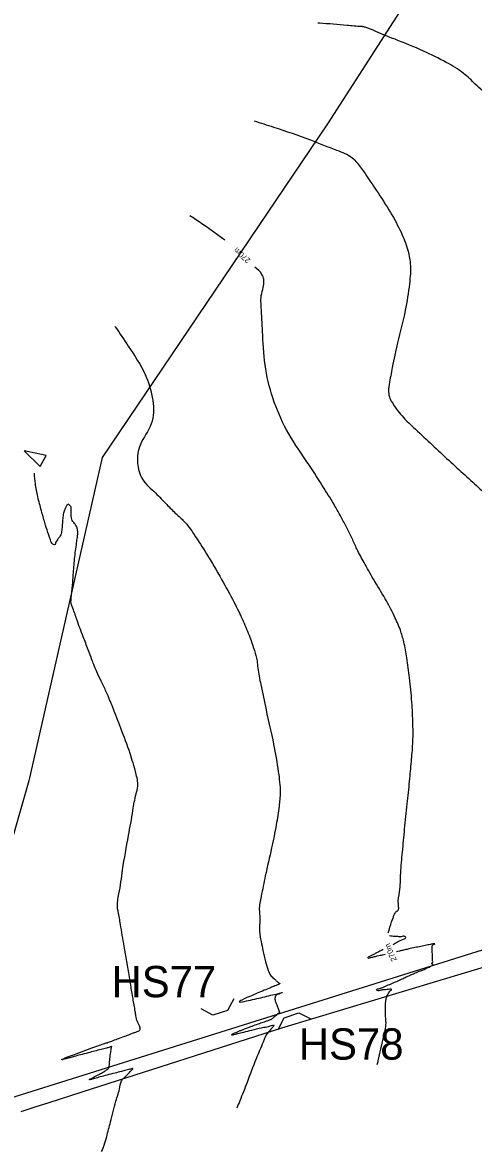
# Model space of a CAD drawing. Extents: x -478495 to -472450, y -1118050 to -1113745.
# Drawn here: x -478028.4 to -477884.4, y -1117519.1 to -1117158.4 of the extents above; entities that cross this region are included whole.
import ezdxf

# ---------------------------------------------------------------- set-up
doc = ezdxf.new("R2010")
doc.units = 0
for name, color, linetype in [('cesty', 7, 'Continuous'), ('hospodářské sjezdy', 7, 'Continuous'), ('hranice kú', 7, 'Continuous'), ('ObPÚ', 7, 'Continuous'), ('silnice', 7, 'Continuous'), ('Vrstevnice_hlavni', 7, 'Continuous'), ('Vrstevnice_popis', 7, 'Continuous'), ('Vrstevnice_vedlejsi', 7, 'Continuous')]:
    doc.layers.add(name, color=color, linetype=linetype)

msp = doc.modelspace()

# ---------------------------------------------------------------- linework, layer by layer
at = {"layer": 'cesty'}
msp.add_line((-478022.76, -1117300.27), (-478020.86, -1117296.75), dxfattribs=at)
msp.add_lwpolyline([(-478020.86, -1117296.75), (-478027.92, -1117295.21), (-478022.76, -1117300.27)], dxfattribs=at)
at = {"layer": 'hospodářské sjezdy'}
for p, q in [((-477960.95, -1117470.32), (-477962.92, -1117474.1)), ((-477967.58, -1117475.57), (-477971.37, -1117473.6)), ((-477962.92, -1117474.1), (-477967.58, -1117475.57)), ((-477944.78, -1117476.38), (-477940.15, -1117474.83)), ((-477940.15, -1117474.83), (-477936.33, -1117476.73)), ((-477946.69, -1117480.2), (-477944.78, -1117476.38))]:
    msp.add_line(p, q, dxfattribs=at)
at = {"layer": 'hranice kú'}
for p, q in [((-477902.65, -1117146.62), (-477931, -1117190.79)), ((-477931, -1117190.79), (-478003, -1117297.4)), ((-478003, -1117297.4), (-478026.36, -1117400.72)), ((-478026.36, -1117400.72), (-478038.56, -1117443.03)), ((-477945.56, -1117479.66), (-477846.46, -1117449.69)), ((-478009.33, -1117500.09), (-477945.56, -1117479.66)), ((-478019.87, -1117503.47), (-478009.33, -1117500.09)), ((-478024.36, -1117504.91), (-478019.87, -1117503.47)), ((-478028.85, -1117506.35), (-478024.36, -1117504.91))]:
    msp.add_line(p, q, dxfattribs=at)
at = {"layer": 'ObPÚ'}
for p, q in [((-477902.65, -1117146.62), (-477931, -1117190.79)), ((-477931, -1117190.79), (-478003, -1117297.4)), ((-478003, -1117297.4), (-478026.36, -1117400.72)), ((-478026.36, -1117400.72), (-478038.56, -1117443.03)), ((-477945.56, -1117479.66), (-477846.46, -1117449.69)), ((-478009.33, -1117500.09), (-477945.56, -1117479.66)), ((-478019.87, -1117503.47), (-478009.33, -1117500.09)), ((-478024.36, -1117504.91), (-478019.87, -1117503.47)), ((-478028.85, -1117506.35), (-478024.36, -1117504.91))]:
    msp.add_line(p, q, dxfattribs=at)
at = {"layer": 'silnice'}
msp.add_lwpolyline([(-478070.5, -1117514.11), (-478065.52, -1117512.47), (-477835.7, -1117440.29), (-477736.73, -1117410.08), (-477702.34, -1117405.05), (-477652.85, -1117401.69), (-477590.78, -1117403.37), (-477332.45, -1117414.28), (-477204.96, -1117416.8), (-477142.05, -1117416.8), (-477096.76, -1117410.08), (-477037.2, -1117399.17), (-476978.49, -1117379.03), (-476883.71, -1117344.63), (-476756.22, -1117298.47), (-476633.76, -1117254.83), (-476588.47, -1117242.24), (-476550.73, -1117234.69), (-476503.76, -1117230.5), (-476424.07, -1117228.82)], dxfattribs=at)
at = {"layer": 'Vrstevnice_hlavni'}
for points in [[(-477974.91, -1117220.07), (-477973.15, -1117221.18), (-477963.79, -1117227.86)], [(-477911.58, -1117449.23), (-477910.48, -1117445.77), (-477910.02, -1117444.45), (-477909.66, -1117443.53), (-477909.39, -1117443.01), (-477909.13, -1117442.62), (-477908.87, -1117442.37), (-477908.62, -1117442.25), (-477908.32, -1117440.18), (-477907.97, -1117436.15), (-477907.57, -1117430.16), (-477907.02, -1117423.49), (-477906.32, -1117416.12), (-477905.47, -1117408.06), (-477904.76, -1117400.83), (-477904.18, -1117394.43), (-477903.73, -1117388.86), (-477903.68, -1117382.56), (-477904.03, -1117375.53), (-477904.76, -1117367.76), (-477905.62, -1117361.34), (-477906.6, -1117356.27), (-477907.7, -1117352.53), (-477909.68, -1117347.95), (-477912.54, -1117342.52), (-477916.29, -1117336.24), (-477919.3, -1117330.94), (-477921.58, -1117326.61), (-477923.12, -1117323.26), (-477924.8, -1117319.85), (-477926.62, -1117316.41), (-477928.58, -1117312.91), (-477932.02, -1117307.31), (-477936.95, -1117299.61), (-477943.37, -1117289.8), (-477947.96, -1117279.65), (-477950.72, -1117269.13), (-477951.66, -1117258.26), (-477952.09, -1117250.2), (-477952, -1117244.93), (-477951.39, -1117242.47), (-477951.36, -1117240.44), (-477951.91, -1117238.85), (-477954.16, -1117236.54)], [(-477915.08, -1117491.33), (-477914.76, -1117490.1), (-477913.06, -1117482.71), (-477912.28, -1117478.03), (-477912.42, -1117476.07), (-477912.49, -1117474.34), (-477912.48, -1117472.84), (-477912.41, -1117471.57), (-477912.24, -1117470.48), (-477911.97, -1117469.55), (-477911.59, -1117468.78), (-477911.22, -1117468.18), (-477910.88, -1117467.73), (-477910.54, -1117467.44), (-477910.6, -1117467.29), (-477911.06, -1117467.27), (-477911.92, -1117467.39), (-477912.88, -1117467.51), (-477913.93, -1117467.6), (-477915.08, -1117467.7), (-477915.21, -1117467.51), (-477914.34, -1117467.04), (-477912.45, -1117466.3), (-477910.62, -1117465.54), (-477908.86, -1117464.77), (-477907.16, -1117463.99), (-477905.79, -1117463.36), (-477904.77, -1117462.89), (-477904.08, -1117462.57), (-477902.9, -1117462.07), (-477901.23, -1117461.38), (-477899.08, -1117460.5), (-477897.75, -1117459.86), (-477897.23, -1117459.45), (-477897.53, -1117459.27), (-477897.67, -1117459.11), (-477897.66, -1117458.96), (-477897.48, -1117458.83), (-477897.4, -1117458.22), (-477897.41, -1117457.13), (-477897.51, -1117455.58), (-477897.56, -1117454.44), (-477897.56, -1117453.72), (-477897.51, -1117453.41), (-477897.34, -1117453.16), (-477897.07, -1117452.94), (-477896.69, -1117452.77), (-477897.01, -1117452.78), (-477898.04, -1117452.96), (-477899.77, -1117453.31), (-477901.6, -1117453.69), (-477903.52, -1117454.1), (-477905.53, -1117454.54), (-477907.03, -1117454.87), (-477908.02, -1117455.08), (-477908.98, -1117455.29)], [(-477909.98, -1117452.97), (-477906.68, -1117451.28), (-477905.98, -1117450.73), (-477906.23, -1117450.47), (-477907.41, -1117450.5), (-477908.49, -1117450.48), (-477909.45, -1117450.43), (-477911.15, -1117450.23)], [(-477913.19, -1117454.61), (-477915.27, -1117455.67), (-477916.24, -1117456.17), (-477917.15, -1117456.64), (-477917.98, -1117457.08), (-477918.11, -1117457.28), (-477917.52, -1117457.23), (-477916.23, -1117456.93), (-477915.1, -1117456.66), (-477914.14, -1117456.44), (-477912.57, -1117456.06)]]:
    msp.add_spline(points, degree=3, dxfattribs=at)
at = {"layer": 'Vrstevnice_vedlejsi'}
for points in [[(-477841.09, -1117162.16), (-477842.18, -1117161.08), (-477846.72, -1117158.46), (-477854.71, -1117154.31), (-477866.14, -1117148.62), (-477874.04, -1117144.69), (-477878.39, -1117142.54), (-477879.19, -1117142.15), (-477879.9, -1117142.05), (-477880.5, -1117142.26), (-477881, -1117142.76), (-477881.56, -1117143.07), (-477882.19, -1117143.18), (-477882.89, -1117143.08), (-477885.58, -1117142.47), (-477890.25, -1117141.34), (-477896.92, -1117139.69), (-477903.18, -1117138.33), (-477909.05, -1117137.27), (-477914.53, -1117136.51), (-477919.96, -1117136.06)], [(-477804.39, -1117419.49), (-477804.46, -1117419.19), (-477804.43, -1117418.83), (-477804.31, -1117418.41), (-477804.09, -1117417.93), (-477803.93, -1117417.61), (-477803.85, -1117417.45), (-477803.84, -1117417.44), (-477803.82, -1117417.43), (-477803.8, -1117417.41), (-477803.79, -1117417.38), (-477803.78, -1117417.35), (-477803.78, -1117417.32), (-477803.8, -1117417.28), (-477803.85, -1117417.04), (-477803.93, -1117416.59), (-477804.04, -1117415.92), (-477804.16, -1117415.49), (-477804.27, -1117415.29), (-477804.39, -1117415.32), (-477804.73, -1117415.28), (-477805.29, -1117415.16), (-477806.06, -1117414.96), (-477806.66, -1117414.18), (-477807.08, -1117412.82), (-477807.33, -1117410.87), (-477807.93, -1117408.58), (-477808.89, -1117405.95), (-477810.21, -1117402.97), (-477810.94, -1117399.86), (-477811.07, -1117396.61), (-477810.62, -1117393.23), (-477810.76, -1117387.65), (-477811.49, -1117379.89), (-477812.83, -1117369.95), (-477814, -1117361.46), (-477815.02, -1117354.42), (-477815.89, -1117348.83), (-477817.22, -1117342.53), (-477819.02, -1117335.5), (-477821.29, -1117327.75), (-477824.63, -1117319.05), (-477829.04, -1117309.41), (-477834.52, -1117298.81), (-477839.07, -1117290.84), (-477842.7, -1117285.48), (-477845.39, -1117282.74), (-477847.12, -1117280.08), (-477847.88, -1117277.51), (-477847.68, -1117275.02), (-477848.82, -1117269.74), (-477851.3, -1117261.68), (-477855.13, -1117250.84), (-477858.13, -1117241.06), (-477860.31, -1117232.33), (-477861.66, -1117224.66), (-477862.37, -1117217.65), (-477862.42, -1117211.32), (-477861.82, -1117205.66), (-477863.51, -1117199.83), (-477867.48, -1117193.82), (-477873.74, -1117187.65), (-477879.16, -1117182.39), (-477883.75, -1117178.06), (-477887.5, -1117174.66), (-477893.02, -1117171.13), (-477900.32, -1117167.5), (-477909.38, -1117163.75), (-477915.57, -1117161.21), (-477918.89, -1117159.89), (-477919.32, -1117159.78), (-477919.64, -1117159.71), (-477919.84, -1117159.66), (-477919.92, -1117159.65), (-477920.01, -1117159.65), (-477920.12, -1117159.64), (-477920.24, -1117159.64), (-477924.72, -1117159.3), (-477933.57, -1117158.6), (-477934.08, -1117158.56)], [(-477954.45, -1117189.78), (-477948.21, -1117191.79), (-477936.42, -1117195.9), (-477928.05, -1117199.17), (-477923.09, -1117201.61), (-477921.54, -1117203.23), (-477918.99, -1117206.68), (-477915.41, -1117211.97), (-477910.83, -1117219.11), (-477907.49, -1117225.39), (-477905.39, -1117230.83), (-477904.54, -1117235.41), (-477904.79, -1117241.92), (-477906.14, -1117250.35), (-477908.6, -1117260.7), (-477910.3, -1117268.59), (-477911.24, -1117274.03), (-477911.43, -1117277.02), (-477909.76, -1117280.71), (-477906.22, -1117285.12), (-477900.83, -1117290.25), (-477895.52, -1117295.22), (-477890.29, -1117300.05), (-477885.15, -1117304.72), (-477880.55, -1117309.01), (-477876.5, -1117312.92), (-477873.01, -1117316.46), (-477870.43, -1117320.23), (-477868.77, -1117324.24), (-477868.03, -1117328.47), (-477866.68, -1117334.33), (-477864.72, -1117341.8), (-477862.15, -1117350.9), (-477860.64, -1117359.03), (-477860.2, -1117366.18), (-477860.82, -1117372.37), (-477861.45, -1117378.87), (-477862.09, -1117385.7), (-477862.73, -1117392.85), (-477863.04, -1117399.45), (-477863, -1117405.49), (-477862.62, -1117410.98), (-477862.35, -1117415.86), (-477862.18, -1117420.16), (-477862.12, -1117423.85), (-477862.02, -1117426.98), (-477861.87, -1117429.54), (-477861.67, -1117431.55), (-477861.33, -1117433.07), (-477860.84, -1117434.12), (-477860.21, -1117434.68), (-477859.74, -1117435.12), (-477859.42, -1117435.43), (-477859.25, -1117435.6), (-477859.8, -1117436), (-477861.09, -1117436.63), (-477863.09, -1117437.48), (-477864.74, -1117438.18), (-477866.04, -1117438.72), (-477867, -1117439.1), (-477868.44, -1117439.71), (-477870.37, -1117440.56), (-477872.79, -1117441.63), (-477874.67, -1117442.45), (-477875.99, -1117443.01), (-477876.76, -1117443.31), (-477877.55, -1117443.63), (-477878.35, -1117443.97), (-477879.16, -1117444.31), (-477879.36, -1117444.45), (-477878.93, -1117444.39), (-477877.88, -1117444.12), (-477877.05, -1117443.91), (-477876.45, -1117443.75), (-477876.07, -1117443.64), (-477874.78, -1117443.3), (-477872.59, -1117442.71)], [(-477998.88, -1117255.56), (-477998.73, -1117255.77), (-477994.61, -1117261.77), (-477989.23, -1117270.88), (-477986.79, -1117279.17), (-477987.3, -1117286.63), (-477990.76, -1117293.26), (-477991.68, -1117299.15), (-477990.07, -1117304.3), (-477985.92, -1117308.7), (-477982.33, -1117312.4), (-477979.31, -1117315.4), (-477976.85, -1117317.7), (-477973.61, -1117321.96), (-477969.59, -1117328.17), (-477964.8, -1117336.34), (-477960.9, -1117343.5), (-477957.9, -1117349.67), (-477955.8, -1117354.83), (-477954.32, -1117359.05), (-477953.47, -1117362.33), (-477953.24, -1117364.66), (-477952.28, -1117369.88), (-477950.6, -1117378), (-477948.19, -1117389), (-477946.69, -1117397.8), (-477946.11, -1117404.41), (-477946.45, -1117408.81), (-477947.35, -1117414.72), (-477948.82, -1117422.14), (-477950.86, -1117431.07), (-477952.18, -1117437.65), (-477952.77, -1117441.86), (-477952.64, -1117443.73), (-477952.59, -1117445.22), (-477952.61, -1117446.35), (-477952.7, -1117447.12), (-477952.71, -1117448.01), (-477952.65, -1117449.02), (-477952.51, -1117450.15), (-477952.16, -1117452.11), (-477951.58, -1117454.9), (-477950.79, -1117458.52), (-477949.91, -1117461.25), (-477948.94, -1117463.09), (-477947.88, -1117464.06), (-477947.14, -1117464.73), (-477946.71, -1117465.1), (-477946.61, -1117465.18), (-477946.49, -1117465.26), (-477946.38, -1117465.35), (-477946.26, -1117465.44), (-477946.23, -1117465.52), (-477946.31, -1117465.61), (-477946.48, -1117465.69), (-477946.65, -1117465.77), (-477946.82, -1117465.85), (-477947, -1117465.93), (-477947.79, -1117466.25), (-477949.2, -1117466.82), (-477951.23, -1117467.63), (-477953.44, -1117468.56), (-477955.82, -1117469.6), (-477958.39, -1117470.77), (-477959.19, -1117471.35), (-477958.24, -1117471.34)], [(-477991.87, -1117477.25), (-477991.93, -1117477.17), (-477992.04, -1117476.68), (-477992.2, -1117475.76), (-477992.41, -1117474.43), (-477993.11, -1117470.28), (-477994.28, -1117463.31), (-477995.94, -1117453.53), (-477997.12, -1117446.59), (-477997.83, -1117442.5), (-477998.06, -1117441.25), (-477997.59, -1117436.78), (-477996.42, -1117429.11), (-477994.55, -1117418.21), (-477993.13, -1117410.14), (-477992.14, -1117404.88), (-477991.6, -1117402.44), (-477992.24, -1117398.12), (-477994.04, -1117391.92), (-477997.02, -1117383.83), (-477999.56, -1117377.28), (-478001.65, -1117372.27), (-478003.31, -1117368.8), (-478004.64, -1117365.89), (-478005.64, -1117363.53), (-478006.32, -1117361.75), (-478007.44, -1117358.79), (-478009, -1117354.66), (-478011, -1117349.36), (-478012.32, -1117345.57), (-478012.94, -1117343.3), (-478012.87, -1117342.55), (-478012.78, -1117341.56), (-478012.66, -1117340.34), (-478012.51, -1117338.9), (-478012.35, -1117337.07), (-478012.18, -1117334.86), (-478012.01, -1117332.28), (-478011.78, -1117329.72), (-478011.48, -1117327.19), (-478011.12, -1117324.69), (-478010.88, -1117322.93), (-478010.74, -1117321.92), (-478010.73, -1117321.65), (-478010.75, -1117321.24), (-478010.82, -1117320.71), (-478010.93, -1117320.04), (-478011.03, -1117319.61), (-478011.11, -1117319.4), (-478011.19, -1117319.43), (-478011.24, -1117319.41), (-478011.27, -1117319.34), (-478011.27, -1117319.22), (-478011.45, -1117318.94), (-478011.79, -1117318.49), (-478012.32, -1117317.88), (-478012.67, -1117317.1), (-478012.86, -1117316.15), (-478012.89, -1117315.03), (-478012.89, -1117314.22), (-478012.87, -1117313.71), (-478012.82, -1117313.51), (-478012.91, -1117313.24), (-478013.13, -1117312.9), (-478013.49, -1117312.49), (-478013.81, -1117312.34), (-478014.09, -1117312.46), (-478014.34, -1117312.83), (-478014.58, -1117313.25), (-478014.82, -1117313.71), (-478015.05, -1117314.21), (-478015.24, -1117314.82), (-478015.39, -1117315.55), (-478015.51, -1117316.4), (-478015.6, -1117317.3), (-478015.67, -1117318.25), (-478015.72, -1117319.26), (-478015.81, -1117320.17), (-478015.93, -1117321), (-478016.1, -1117321.75), (-478016.33, -1117322.36), (-478016.62, -1117322.85), (-478016.97, -1117323.22), (-478017.34, -1117323.74), (-478017.75, -1117324.43), (-478018.18, -1117325.27), (-478018.76, -1117325.03), (-478019.47, -1117323.71), (-478020.32, -1117321.3), (-478021.28, -1117318.2), (-478022.35, -1117314.39), (-478023.54, -1117309.88), (-478024.3, -1117305.74), (-478024.62, -1117302.33)], [(-477958.24, -1117471.34), (-477955.54, -1117470.74), (-477952.92, -1117470.14), (-477950.38, -1117469.54), (-477947.93, -1117468.94), (-477946.28, -1117468.54), (-477945.45, -1117468.34), (-477945.41, -1117468.34), (-477945.71, -1117468.47), (-477946.34, -1117468.74), (-477947.3, -1117469.14), (-477947.73, -1117469.92), (-477947.64, -1117471.08), (-477947.02, -1117472.61), (-477946.6, -1117473.71), (-477946.38, -1117474.37), (-477946.35, -1117474.6), (-477946.37, -1117474.77), (-477946.45, -1117474.9), (-477946.56, -1117474.97), (-477946.68, -1117475.04), (-477946.78, -1117475.1), (-477946.88, -1117475.16), (-477946.94, -1117475.21), (-477946.97, -1117475.24), (-477946.96, -1117475.27), (-477947.16, -1117475.47), (-477947.57, -1117475.83), (-477948.19, -1117476.36), (-477948.67, -1117476.75), (-477949, -1117476.98), (-477949.19, -1117477.05), (-477949.47, -1117477.16), (-477949.83, -1117477.28), (-477950.27, -1117477.44), (-477951.24, -1117477.77), (-477952.72, -1117478.29), (-477954.72, -1117479), (-477956.35, -1117479.6), (-477957.6, -1117480.08), (-477958.48, -1117480.44), (-477959.41, -1117480.83), (-477960.4, -1117481.26), (-477961.45, -1117481.7), (-477961.6, -1117481.87), (-477960.87, -1117481.76), (-477959.24, -1117481.36), (-477957.1, -1117480.84), (-477954.45, -1117480.2), (-477951.28, -1117479.44), (-477949.18, -1117478.98), (-477948.14, -1117478.83), (-477948.17, -1117478.99), (-477948.49, -1117479.41), (-477949.09, -1117480.08), (-477949.98, -1117481.02), (-477951.54, -1117484.16), (-477953.78, -1117489.53), (-477956.68, -1117497.1), (-477959, -1117502.97), (-477959.94, -1117505.27)], [(-478003.14, -1117519.11), (-478003.13, -1117519.09), (-478002.85, -1117518.53), (-478002.56, -1117517.87), (-478002.28, -1117517.09), (-478001.52, -1117514.37), (-478000.29, -1117509.7), (-477998.59, -1117503.07), (-477997.31, -1117498.53), (-477996.45, -1117496.06), (-477996.01, -1117495.66), (-477995.49, -1117495.16), (-477994.9, -1117494.56), (-477994.22, -1117493.84), (-477993.71, -1117493.3), (-477993.36, -1117492.95), (-477993.18, -1117492.76), (-477993.12, -1117492.66), (-477993.18, -1117492.63), (-477993.36, -1117492.68), (-477993.77, -1117492.78), (-477994.43, -1117492.95), (-477995.32, -1117493.19), (-477996.79, -1117493.56), (-477998.85, -1117494.08), (-478001.47, -1117494.75), (-478003.61, -1117495.31), (-478005.26, -1117495.76), (-478006.42, -1117496.1), (-478007, -1117496.22), (-478006.99, -1117496.12), (-478006.41, -1117495.81), (-478005.71, -1117495.44), (-478004.89, -1117495.01), (-478003.97, -1117494.52), (-478003.17, -1117494.09), (-478002.51, -1117493.71), (-478001.97, -1117493.37), (-478001.54, -1117493.09), (-478001.19, -1117492.85), (-478000.94, -1117492.65), (-478000.75, -1117492.19), (-478000.63, -1117491.47), (-478000.58, -1117490.49), (-478000.5, -1117489.49), (-478000.39, -1117488.49), (-478000.24, -1117487.47), (-478000.13, -1117486.7), (-478000.05, -1117486.19), (-478000, -1117485.94), (-477999.97, -1117485.77), (-477999.94, -1117485.67), (-477999.93, -1117485.66), (-478000.49, -1117485.8), (-478001.62, -1117486.09), (-478003.33, -1117486.53), (-478005.28, -1117487.04), (-478007.48, -1117487.61), (-478009.92, -1117488.25), (-478011.86, -1117488.77), (-478013.3, -1117489.16), (-478014.25, -1117489.42), (-478014.98, -1117489.62), (-478015.5, -1117489.74), (-478015.81, -1117489.8), (-478015.84, -1117489.76), (-478015.58, -1117489.61), (-478015.04, -1117489.35), (-478014.55, -1117489.14), (-478014.12, -1117488.95), (-478013.74, -1117488.8), (-478012.41, -1117488.31), (-478010.11, -1117487.46), (-478006.85, -1117486.27), (-478004.32, -1117485.36), (-478002.5, -1117484.72), (-478001.41, -1117484.37), (-477999.92, -1117483.84), (-477998.03, -1117483.15), (-477995.74, -1117482.29), (-477994.05, -1117481.65), (-477992.97, -1117481.25), (-477992.48, -1117481.07), (-477992, -1117480.88), (-477991.51, -1117480.68), (-477991.03, -1117480.47), (-477990.84, -1117480.01), (-477990.96, -1117479.28), (-477991.38, -1117478.3), (-477991.68, -1117477.62), (-477991.87, -1117477.25)]]:
    msp.add_spline(points, degree=3, dxfattribs=at)

# ---------------------------------------------------------------- texts
at = {"layer": 'hospodářské sjezdy'}
for s, p in [('HS77', (-477999.97, -1117469.84)), ('HS78', (-477940.14, -1117489.78))]:
    msp.add_text(s, height=10, rotation=360, dxfattribs=at).set_placement(p)
at = {"layer": 'Vrstevnice_popis'}
for height, rotation, p in [(1.799, 137.9834, (-477954.96, -1117234.6)), (1.8, 113.2511, (-477908.54, -1117458.59))]:
    msp.add_text(' 270m ', height=height, rotation=rotation, dxfattribs=at).set_placement(p)

doc.saveas('drawing.dxf')
